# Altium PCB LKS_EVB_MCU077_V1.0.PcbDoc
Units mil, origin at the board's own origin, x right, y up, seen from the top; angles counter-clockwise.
Board outline 2625 x 1560 mil, 2 copper layers (Top Layer, Bottom Layer); 32 components, 57 nets, 146 pads, 20 vias.
Unrouted connection lines stored in the file: 4.
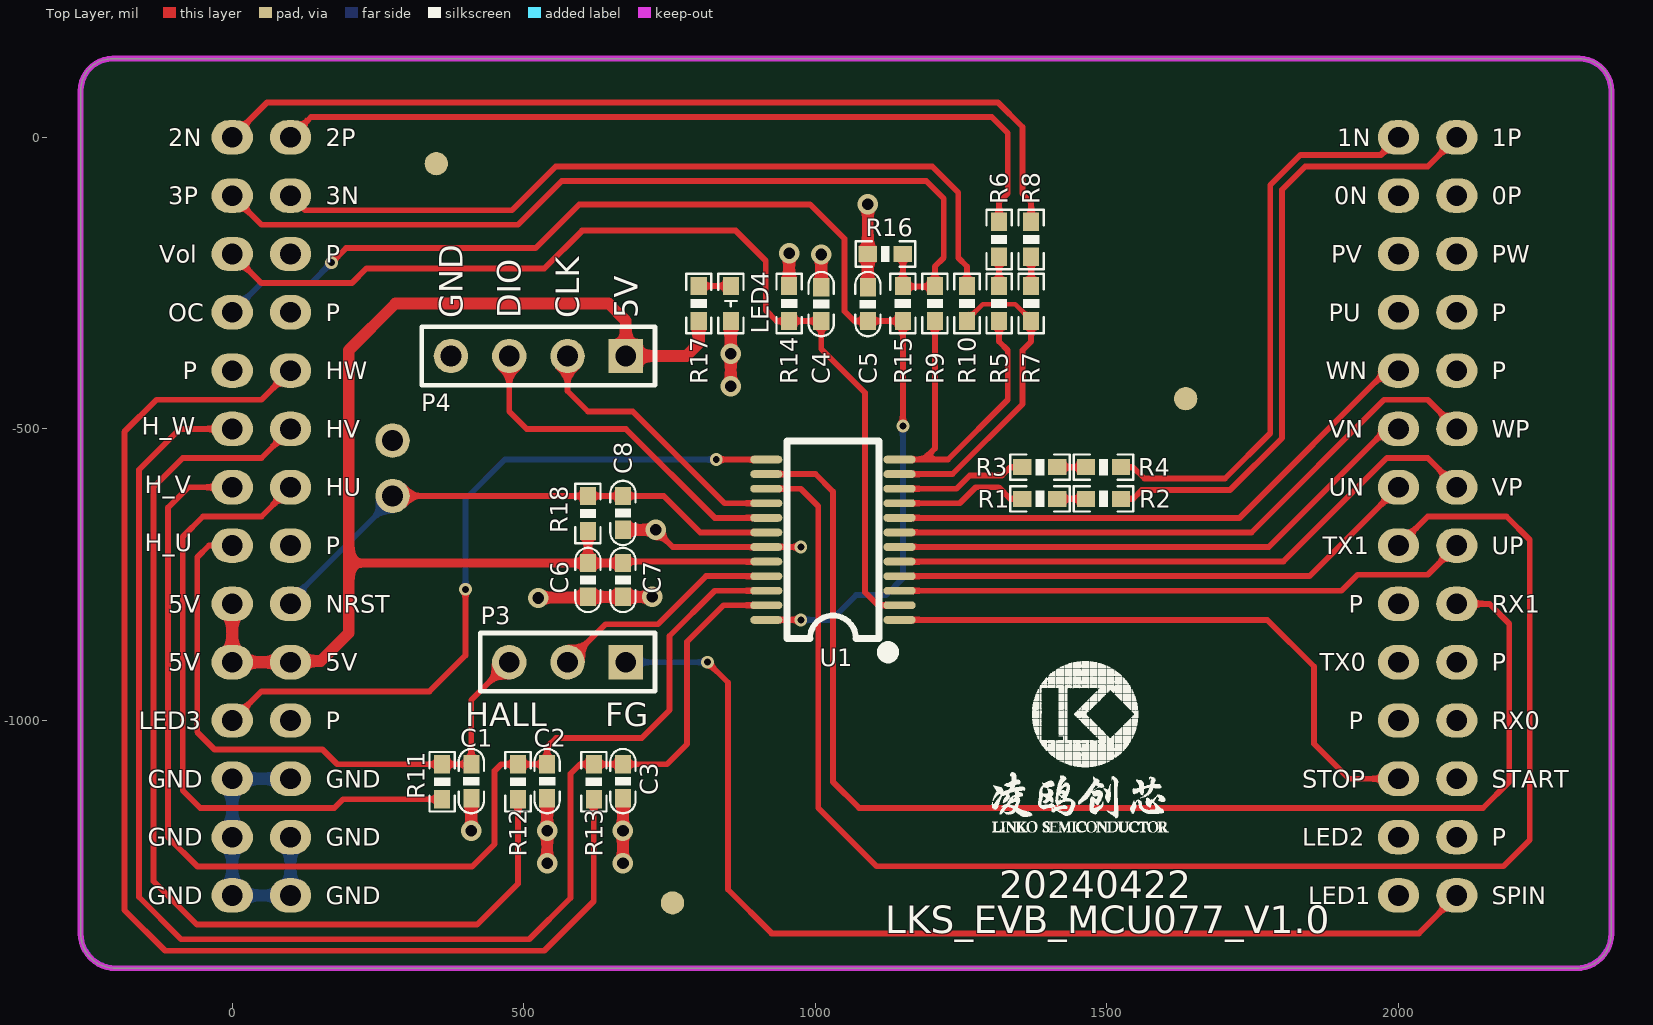
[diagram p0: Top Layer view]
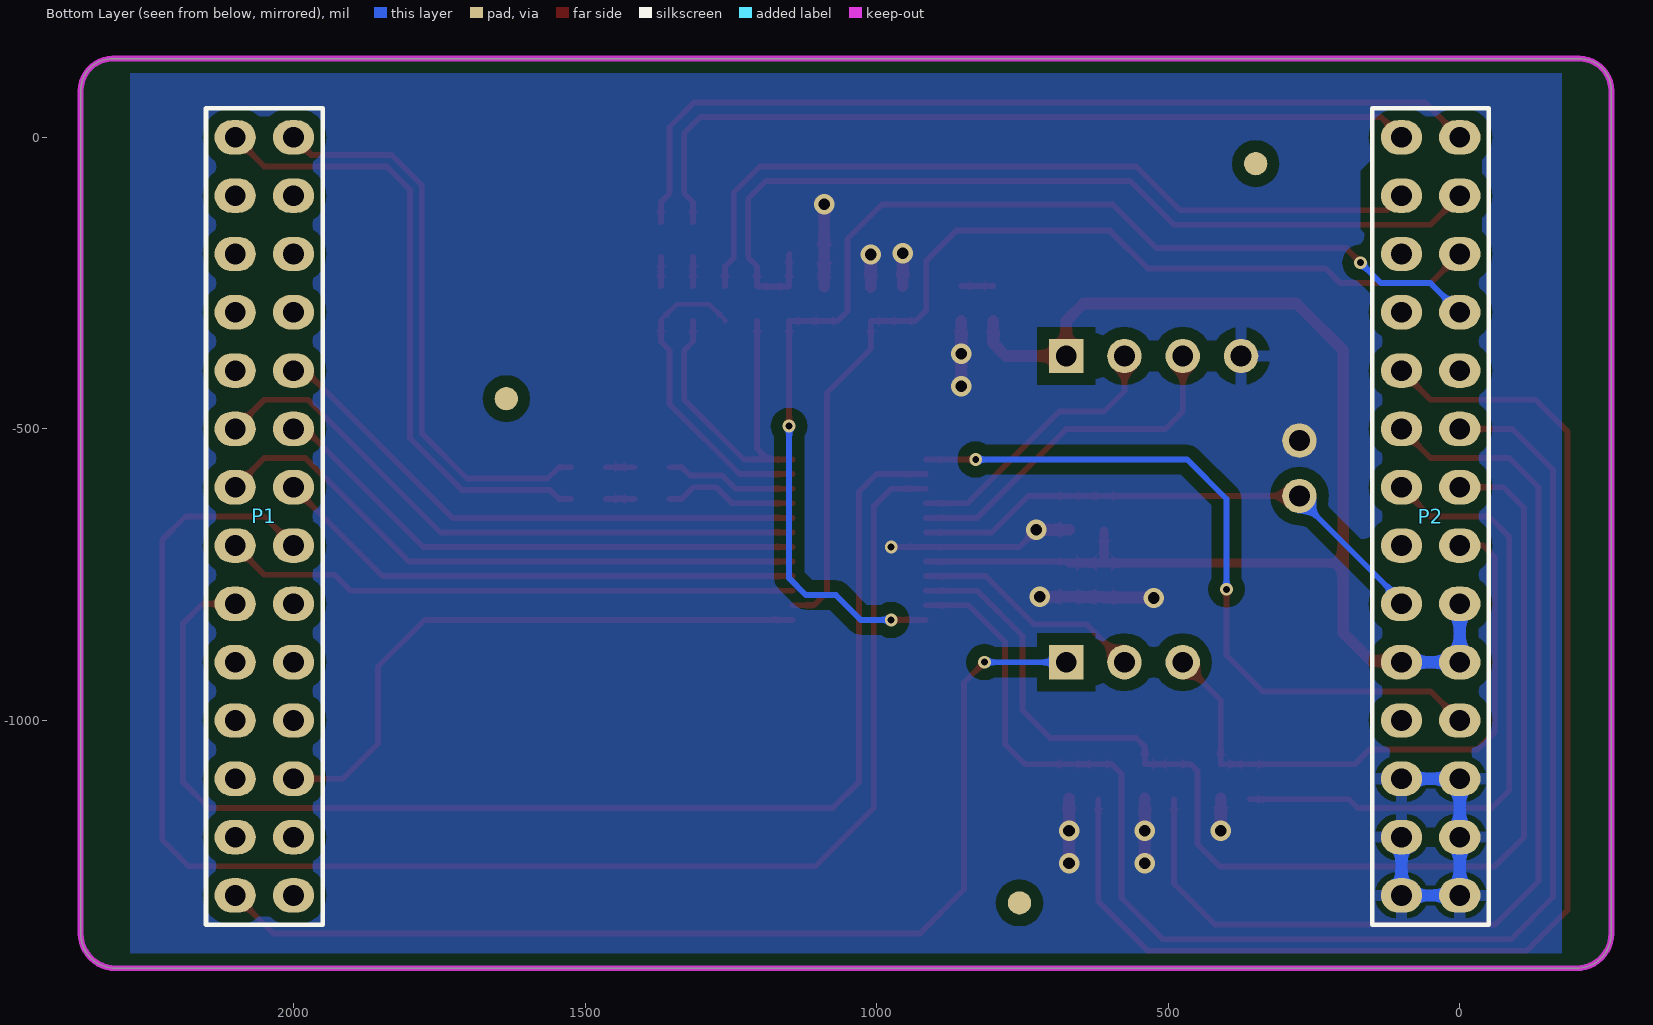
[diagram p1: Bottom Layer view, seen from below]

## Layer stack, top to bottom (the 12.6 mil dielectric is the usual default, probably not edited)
Top Solder: solder mask 0.4, Solder Resist, Dk 3.5
Top Layer: signal copper 1.4
Dielectric1: dielectric 12.6, FR-4, Dk 4.8
Bottom Layer: signal copper 1.4
Bottom Solder: solder mask 0.4, Solder Resist, Dk 3.5

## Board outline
-260,-1365 -260,80 cw(c-205,80) -205,135 2310,135 cw(c2310,80) 2365,80 2365,-1365 cw(c2305,-1365) 2305,-1425 -200,-1425 cw(c-200,-1365)

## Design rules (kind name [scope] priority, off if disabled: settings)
Clearance Clearance_2 [InPolygon] p1: gap=20 ignorepadtopadclearanceinfootprint=FALSE except(0: Arc-Hole Track-Hole SMDPad-Hole THPad-Hole Via-Hole Fill-Hole Poly-Hole Region-Hole Text-Hole)
Clearance Clearance_1 [All] p2: gap=7.87 ignorepadtopadclearanceinfootprint=FALSE except(0: Arc-Hole Track-Hole SMDPad-Hole THPad-Hole Via-Hole Fill-Hole Poly-Hole Region-Hole Text-Hole)
ComponentClearance [All] p1: gap=0 collisioncheckmode=3 verticalgap=0 showdistances=FALSE
FabricationTestpoint [(IsPad And (OnTopLayer Or OnBottomLayer))] p1: side=3 testpointundercomponent=TRUE minsize=40 maxsize=100 preferedsize=60 minholesize=0 maxholesize=40 preferedholesize=32 testpointgrid=1 allowsidetop=TRUE allowsidebottom=TRUE usegrid=TRUE gridtolerance=0.01
PolygonConnect PolygonConnect_2 [All vs HasFootprint('HDR 1X4')] p1: connectstyle=Relief reliefconductorwidth=20 reliefentries=4 polygonreliefangle="90 Angle" airgapwidth=20
PolygonConnect PolygonConnect_1 [HasFootprint('HDR 2X14 底层') vs InNet('GND')] p2: connectstyle=Relief reliefconductorwidth=20 reliefentries=4 polygonreliefangle="90 Angle" airgapwidth=10
PolygonConnect [All] p3: connectstyle=Direct reliefconductorwidth=10 reliefentries=4 polygonreliefangle="90 Angle" airgapwidth=10
RoutingVias [All] p1: holewidth=28 width=50 viastyle="Through Hole" minholewidth=28 minwidth=50 maxholewidth=28 maxwidth=50
SilkToSolderMaskClearance SilkscreenOverComponentPads [IsPad] p1: minsilkscreentomaskgap=10 clearancetoexposedcopper=TRUE
SolderMaskExpansion [All] p1: expansion=4 istentingtop=FALSE
Width [All] p1: maxlimit=100 minlimit=1 preferedwidth=10
27 further rules are at their usual default settings.

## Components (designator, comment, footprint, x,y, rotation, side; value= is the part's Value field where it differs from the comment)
C1 "10nF/16V" 0603C 410,-1104 r270 top
C2 "10nF/16V" 0603C 540,-1104 r270 top
C3 "10nF/16V" 0603C 670,-1104 r270 top
C4 "100nF/50V" 0603C 1010,-285.94 r270 top
C5 "1nF/50V" 0603C 1090,-285.94 r270 top
C6 "10uF/10V" 0603C 610,-759.05 r90 top
C7 "100nF/50V" 0603C 670,-759.05 r90 top
C8 "100nF/50V" 0603C 670,-644 r270 top
LED4 "LED" "LED 0603R" 855,-285 r270 top
P1 "Header 14X2A" "HDR 2X14 底层" 2000,0 r180 bottom locked
P2 "Header 14X2A" "HDR 2X14 底层" 0,0 r180 bottom locked
P3 "Header 3" "HDR 1X3" 675,-900 r180 top
P4 "Header 4" "HDR 1X4" 675,-375 r180 top locked
R1 "20K1%" 0603R 1385,-620 r180 top value=K
R2 "20K1%" 0603R 1494.06,-620 r180 top value=K
R3 "20K1%" 0603R 1385,-565.6 r180 top value=K
R4 "20K1%" 0603R 1494.06,-565.6 r180 top value=K
R5 "20K1%" 0603R 1315,-285 r270 top value=K
R6 "20K1%" 0603R 1315,-175 r270 top value=K
R7 "20K1%" 0603R 1370,-285 r270 top value=K
R8 "20K1%" 0603R 1370,-175 r270 top value=K
R9 "1K1%" 0603R 1205,-285 r270 top value=K
R10 "1K1%" 0603R 1260,-285 r270 top value=K
R11 "2K" 0603R 360,-1105 r90 top value=K
R12 "2K" 0603R 490,-1105 r90 top value=K
R13 "2K" 0603R 620,-1105 r90 top value=K
R14 "1K1%" 0603R 955,-285 r270 top value=K
R15 "1K1%" 0603R 1150,-285 r90 top value=K
R16 "10R" 0603R 1120,-200 r180 top value=K
R17 "330R" 0603R 800,-285 r90 top value=330
R18 "20K" 0603R 610,-645 r270 top value=K
U1 "LKS32MC077MBS8" SSOP24 1030,-690 r180 top

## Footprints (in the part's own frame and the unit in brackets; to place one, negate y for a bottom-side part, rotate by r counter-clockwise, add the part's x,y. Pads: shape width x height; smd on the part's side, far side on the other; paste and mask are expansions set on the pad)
0603C [mm] "电容"
  rect 0.8x0.7 smd: 1(-0.737,0) 2(0.738,0)
  silkscreen extent -1.4,-0.55 1.4,0.55, body extent -0.8,-0.41 0.8,0.41, height 0.81
0603R [mm] "电阻"
  rect 0.8x0.7 smd: 1(-0.762,0) 2(0.762,0)
  silkscreen extent -1.3,-0.55 1.3,0.55, body extent -0.8,-0.4 0.8,0.4, height 0.45
"HDR 1X3" [mm] "单排针 2.54mm"
  rect 1.5x1.5 hole 0.9: 1(0,0)
  round 1.5 hole 0.9: 2(2.54,0) 3(5.08,0)
  silkscreen extent -1.27,-1.27 6.35,1.27, body extent -1.27,-1.27 6.35,1.27, height 8.5
"HDR 1X4" [mm] "单排针 2.54mm"
  rect 1.5x1.5 hole 0.9: 1(0,0)
  round 1.5 hole 0.9: 2(2.54,0) 3(5.08,0) 4(7.62,0)
  silkscreen extent -1.27,-1.27 8.89,1.27, body extent -1.27,-1.27 8.89,1.27, height 8.5
"HDR 2X14 底层" [mm] "双排针 2.54mm 底层"
  oval 1.8x1.5 hole 0.9: 1(0,0) 2(0,-2.54) 3(0,-5.08) 4(0,-7.62) 5(0,-10.16) 6(0,-12.7) 7(0,-15.24) 8(0,-17.78) 9(0,-20.32) 10(0,-22.86) 11(0,-25.4) 12(0,-27.94) 13(0,-30.48) 14(0,-33.02) 15(-2.54,0) 16(-2.54,-2.54) 17(-2.54,-5.08) 18(-2.54,-7.62) 19(-2.54,-10.16) 20(-2.54,-12.7) 21(-2.54,-15.24) 22(-2.54,-17.78) 23(-2.54,-20.32) 24(-2.54,-22.86) 25(-2.54,-25.4) 26(-2.54,-27.94) 27(-2.54,-30.48) 28(-2.54,-33.02)
  silkscreen extent -3.81,-34.29 1.27,1.27, body extent -3.81,-34.29 1.27,1.27, height 8.5
"LED 0603R" [mm] "LED"
  rect 0.8x0.7 smd: 1(-0.762,0) 2(0.762,0)
  silkscreen extent -1.3,-0.55 1.3,0.55, body extent -0.8,-0.4 0.8,0.4, height 0.47
SSOP24 [mm] "e=0.635mm"
  oval 1.4x0.34 smd: 1(-2.9,3.492) 2(-2.9,2.857) 3(-2.9,2.222) 4(-2.9,1.587) 5(-2.9,0.952) 6(-2.9,0.317) 7(-2.9,-0.318) 8(-2.9,-0.953) 9(-2.9,-1.588) 10(-2.9,-2.223) 11(-2.9,-2.858) 12(-2.9,-3.492) 13(2.9,-3.492) 14(2.9,-2.857) 15(2.9,-2.222) 16(2.9,-1.587) 17(2.9,-0.952) 18(2.9,-0.317) 19(2.9,0.318) 20(2.9,0.953) 21(2.9,1.588) 22(2.9,2.223) 23(2.9,2.858) 24(2.9,3.492)
  silkscreen extent -2.5,-4.3 2,5, body extent -3.22,-3.84 3.19,3.96, height 1.03

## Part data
C1 C2 C3: library part CAP, "Capacitor"
C4 C5 C6 C7 C8: library part C, "Capacitor"
LED4: "LED_Light"
P1 P2: "Header, 14-Pin, Dual row"
P3: "Header, 3-Pin"
P4: "Header, 4-Pin"
R1 R2 R3 R4 R5 R6 R7 R8 R9 R10 R11 R12 R13 R14 R15 R16 R17 R18: library part Res, "Resistor"
U1: "芯片"

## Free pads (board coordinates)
  round 59 hole 36: 0(275,-520.01) 1(275,-615)
  round 40 all layers, no hole: 2(1635,-448.14) 3(755,-1312.82) 4(350,-45)

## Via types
v1: diameter 35, hole 20, Top Layer to Bottom Layer, 13 vias
v2: diameter 22, hole 12, Top Layer to Bottom Layer, 7 vias

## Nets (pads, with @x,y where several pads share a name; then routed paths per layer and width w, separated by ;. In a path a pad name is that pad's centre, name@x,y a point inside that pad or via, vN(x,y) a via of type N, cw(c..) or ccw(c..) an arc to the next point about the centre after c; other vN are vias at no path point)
+5V: C6.2 C7.2 P2.9 P2.10 P2.24 P4.1 R17.1 R18.2 U1.20 | length 2530.6
  Top Layer w10: C7.2 672.5,-727.5 U1.20
  Top Layer w15: 200,-730 C6.2 ; R18.2 C6.2 ; C7.2 C6.2
  Top Layer w20: P2.9 P2.10 P2.24 102.03,-897.97 152.03,-897.97 200,-850 200,-730 200,-365 280,-285 645.31,-285 675,-314.68 P4.1 778.35,-375 800,-353.35 R17.1
  Bottom Layer w20: P2.9 P2.10 P2.24
GND: C1.2 C2.2 C3.2 C4.1 C5.1 C6.1 C7.1 C8.2 LED4.2 P2.12 P2.13 P2.14 P2.16 P2.26 P2.27 P2.28 P4.4 pad.0 R10.1 R14.1 R16.2 U1.19 | length 3029.4
  Top Layer w10: P2.16 125,-125 479.64,-125 554.64,-50 1200.36,-50 1245,-94.64 1245,-206.5 1260,-221.5 R10.1 ; v1(726,-673.05) 755.45,-702.5 U1.19 v2(975,-702.5)
  Top Layer w20: v1(410,-1189.06) C1.2 ; v1(525,-790) 525.97,-789.03 609.03,-789.03 C6.1 C7.1 v1(720,-788.05) ; v1(540,-1245.06) v1(540,-1189.06) C2.2 ; v1(670,-1245.06) v1(670,-1189.06) C3.2 ; C8.2 v1(726,-673.05) ; v1(855,-427) v1(855,-371) LED4.2 ; R14.1 v1(955,-199) ; C4.1 v1(1010,-200.94) ; C5.1@1090,-255.94 v1(1090,-115)
  Bottom Layer w20: P2.27 P2.28 P2.14 P2.13 P2.12 P2.26
HALL_U: C1.1 P2.8 P3.3 R11.2 | length 1063
  Top Layer w10: P2.8 -40,-700 -60,-720 -60,-1020 -30,-1050 155,-1050 180,-1075 R11.2 C1.1 410,-965 P3.3
HALL_V: C2.1 P2.7 R12.2 U1.22 | length 2097.8
  Top Layer w10: P2.7 -75,-600 -110,-635 -110,-1200 -59.36,-1250.64 411.01,-1250.64 450,-1211.65 450,-1086.28 461.28,-1075 R12.2 C2.1 540,-1045 555,-1030 702.22,-1030 750,-982.22 750,-855 827.5,-777.5 U1.22
HALL_W: C3.1 P2.6 R13.2 U1.23 | length 2492.3
  Top Layer w10: P2.6 -90,-500 -160,-570 -160,-1302.87 -87.87,-1375 509.25,-1375 580,-1304.25 580,-1091.28 596.28,-1075 R13.2 C3.1 745.54,-1075 780,-1040.54 780,-865 842.5,-802.5 U1.23
HU: P2.21 R11.1 | length 1118.8
  Top Layer w10: P2.21 50,-650 -50,-650 -85,-685 -85,-1120 -55,-1150 175,-1150 190,-1135 R11.1
HV: P2.20 R12.1 | length 1781.9
  Top Layer w10: P2.20 50,-550 -85,-550 -135,-600 -135,-1275.64 -60.64,-1350 420,-1350 490,-1280 R12.1
HW: P2.19 R13.1 | length 2192.7
  Top Layer w10: P2.19 50,-450 -130,-450 -185,-505 -185,-1325 -115,-1395 535,-1395 620,-1310 R13.1
LED1: P1.14
LED2: P1.13
LED3: P2.11 U1.13 | length 1258.4
  Top Layer w10: P2.11 50,-950 338.35,-950 400,-888.35 v2(400,-775) ; v2(830,-552.5) U1.13
  Bottom Layer w10: v2(400,-775) 400,-620 467.5,-552.5 v2(830,-552.5)
NetLED4_1: LED4.1 R17.2 | length 55
  Top Layer w10: R17.2 LED4.1
NetP3_2: P3.2 U1.21 | length 401.9
  Top Layer w10: P3.2 640,-835 730,-835 812.5,-752.5 U1.21
NetR1_1: R1.1 R2.2 | length 49.1
  Top Layer w10: R1.1 R2.2
NetR3_1: R3.1 R4.2 | length 49.1
  Top Layer w10: R3.1 R4.2
NetR5_1: R5.1 R6.2 | length 50
  Top Layer w10: R5.1 R6.2
NetR7_1: R7.1 R8.2 | length 50
  Top Layer w10: R7.1 R8.2
NRST: C8.1 P2.23 pad.1 R18.1 U1.18 | length 924.2
  Top Layer w10: pad.1 R18.1 C8.1 740,-615 802.5,-677.5 U1.18
  Bottom Layer w10: P2.23 100,-795 275,-620 pad.1
OC: C5.2 P2.4 R15.1 U1.24 | length 2087
  Top Layer w10: v2(170,-215) 195,-190 520,-190 595,-115 991.01,-115 1050,-173.99 1050,-298.15 1066.85,-315 C5.2 R15.1 v2(1150,-495) ; U1.24 v2(975,-827.5)
  Bottom Layer w10: P2.4 50,-250 135,-250 v2(170,-215) ; v2(975,-827.5) 1027.13,-827.5 1069.63,-785 1120.93,-785 1150,-755.93 v2(1150,-495)
OPA2_IN: R3.2 U1.10 | length 226.1
  Top Layer w10: U1.10 1242.07,-602.5 1264.57,-580 1319.85,-580 1334.25,-565.6 R3.2
OPA2_IP: R1.2 U1.9 | length 230.5
  Top Layer w10: U1.9 1247.5,-627.5 1275,-600 1314.25,-600 1334.25,-620 R1.2
OPA3_IN: R7.2 R10.2 U1.11 | length 545.6
  Top Layer w8: R10.2 1260,-313.03 1287.09,-285.94 1342.91,-285.94 1370,-313.03 R7.2
  Top Layer w10: U1.11 1235,-577.5 1355,-457.5 1355,-365 1370,-350 R7.2
OPA3_IP: R5.2 R9.2 U1.12 | length 614.9
  Top Layer w10: U1.12 1185.84,-552.5 ; R9.2 1205,-533.34 1185.84,-552.5 ; R5.2 1315,-350 1330,-365 1330,-450 1227.5,-552.5 1185.84,-552.5
P0.0: P2.22
P0.4: P1.27
P0.14: P1.11
P1.3: P1.24
P1.10: P1.19
P1.11: P1.18
P2.1: P2.18
P2.2: P2.5
P2.7: P1.9
P2.10: P2.17
P3.2: P2.25
PGND: P1.1 P1.2 P2.1 P2.2 R4.1 R8.1 R9.1 R15.2 R16.1 | length 4094.2
  Top Layer w10: P2.2 50,-150 490,-150 565,-75 1190,-75 1220,-105 1220,-206.26 1205,-221.26 R9.1 1204.06,-255.94 1150,-255.94 1150,-200.94 R16.1@1149.06,-200 ; P2.1 60,60 1312.86,60 1355,17.86 1355,-96.5 1370,-111.5 R8.1 ; R4.1 1544.8,-565.6 1564.21,-585 1702.5,-585 1780,-507.5 1780,-81.72 1831.72,-30 1970,-30 P1.1
PU: P1.4
PV: P1.3
PW: P1.17
RXD0: P1.25
RXD1: P1.23 U1.14 | length 2196.4
  Top Layer w10: U1.14 1000,-577.5 1030,-607.5 1030,-1105 1075,-1150 2145,-1150 2190,-1105 2190,-834.14 2155.86,-800 P1.23
SPIN: P1.28 P3.1 | length 1852.5
  Top Layer w10: v2(815,-900) 850,-935 850,-1290 925,-1365 2035,-1365 P1.28
  Bottom Layer w10: P3.1 v2(815,-900)
START1: P1.26
STOP1: P1.12 U1.1 | length 1046.3
  Top Layer w10: U1.1 1775,-827.5 1855,-907.5 1855,-1040 1915,-1100 P1.12
SWCLK: P4.2 U1.16 | length 480.6
  Top Layer w10: P4.2 575,-435 610,-470 686.74,-470 844.24,-627.5 U1.16
SWDIO: P4.3 U1.17 | length 611.4
  Top Layer w10: P4.3 475,-470 505,-500 675,-500 827.5,-652.5 U1.17
TXD0: P1.10
TXD1: P1.8 U1.15 | length 2676.4
  Top Layer w10: U1.15 975,-602.5 1005,-632.5 1005,-1150 1105,-1250 2180,-1250 2225,-1205 2225,-690 2185,-650 2050,-650 P1.8
UN: P1.7 U1.4 | length 919
  Top Layer w10: U1.4 1847.5,-752.5 P1.7
UP: P1.22 U1.3 | length 987.9
  Top Layer w10: U1.3 1902.18,-777.5 1929.68,-750 2050,-750 P1.22
UP-: P2.15 R6.1 | length 1414.6
  Top Layer w10: P2.15 135,35 1302.5,35 1330,7.5 1330,-96.26 1315,-111.26 R6.1
VN: P1.6 U1.6 | length 939.7
  Top Layer w10: U1.6 1777.5,-702.5 1980,-500 P1.6
VOL_ADC: C4.2 P2.3 R14.2 U1.2 | length 1746.6
  Top Layer w10: P2.3 50,-250 205,-250 230,-225 535,-225 600,-160 863.43,-160 915,-211.57 915,-296.65 933.35,-315 R14.2 C4.2 1010,-363.05 1085,-438.05 1085,-780 1107.5,-802.5 U1.2
VP: P1.21 U1.5 | length 1050.1
  Top Layer w10: U1.5 1802.5,-727.5 1980,-550 2050,-550 P1.21
VP-: P1.15 R2.1 | length 1082.2
  Top Layer w10: R2.1 1544.8,-620 1559.8,-605 1710.78,-605 1800,-515.78 1800,-90 1840,-50 2050,-50 P1.15
WN: P1.5 U1.8 | length 960.4
  Top Layer w10: U1.8 1727.5,-652.5 1980,-400 P1.5
WP: P1.20 U1.7 | length 1070.8
  Top Layer w10: U1.7 1747.78,-677.5 1975.28,-450 2050,-450 P1.20
WP-: P1.16

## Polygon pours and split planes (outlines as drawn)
GND on Bottom Layer "Bottom Layer-No Net 1" (solid, remove dead copper, pour order 12): -175,135 -175,-1425 2280,-1425 2280,135

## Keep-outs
Keep-Out Layer:
  the board outline again, w10

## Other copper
Bottom Layer:
  pour cut-out: -37.49,-37.49 150,-37.49 170,-57.49 170,-157.49 154.98,-172.51 -37.49,-172.51

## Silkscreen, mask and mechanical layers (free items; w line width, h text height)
Top Overlay:
  drawing of 144 lines, arcs and shapes, not listed
  text "2N" at -110,-15 h30
  text "2P" at 160,-15 h30
  text "1N" at 1895,-15 h30
  text "1P" at 2160,-15 h30
  text "3P" at -110,-115 h30
  text "3N" at 160,-115 h30
  text "0N" at 1890,-115 h30
  text "0P" at 2160,-115 h30
  text "Vol" at -125,-215 h30
  text "P" at 160,-215 h30
  text "PV" at 1885,-215 h30
  text "PW" at 2160,-215 h30
  text "GND" at 395,-310 h40 r90
  text "DIO" at 495,-310 h40 r90
  text "CLK" at 595,-310 h40 r90
  text "5V" at 695,-310 h40 r90
  text "OC" at -110,-315 h30
  text "P" at 160,-315 h30
  text "PU" at 1880,-315 h30
  text "P" at 2160,-315 h30
  text "P" at -85,-415 h30
  text "HW" at 160,-415 h30
  text "WN" at 1875,-415 h30
  text "P" at 2160,-415 h30
  text "H_W" at -155,-510 h30
  text "HV" at 160,-515 h30
  text "VN" at 1880,-515 h30
  text "WP" at 2160,-515 h30
  text "H_V" at -150,-610 h30
  text "HU" at 160,-615 h30
  text "UN" at 1880,-615 h30
  text "VP" at 2160,-615 h30
  text "H_U" at -150,-710 h30
  text "P" at 160,-715 h30
  text "TX1" at 1870,-715 h30
  text "UP" at 2160,-715 h30
  text "5V" at -110,-815 h30
  text "NRST" at 160,-815 h30
  text "P" at 1915,-815 h30
  text "RX1" at 2160,-815 h30
  text "5V" at -110,-915 h30
  text "5V" at 160,-915 h30
  text "TX0" at 1865,-915 h30
  text "P" at 2160,-915 h30
  text "HALL" at 400,-1010 h40
  text "FG" at 640,-1010 h40
  text "LED3" at -160,-1015 h30
  text "P" at 160,-1015 h30
  text "P" at 1915,-1015 h30
  text "RX0" at 2160,-1015 h30
  text "GND" at -145,-1115 h30
  text "GND" at 160,-1115 h30
  text "STOP" at 1835,-1115 h30
  text "START" at 2160,-1115 h30
  text "GND" at -145,-1215 h30
  text "GND" at 160,-1215 h30
  text "LED2" at 1835,-1215 h30
  text "P" at 2160,-1215 h30
  text "GND" at -145,-1315 h30
  text "GND" at 160,-1315 h30
  text "LED1" at 1845,-1315 h30
  text "SPIN" at 2160,-1315 h30
  text "20240422" at 1315,-1320 h80
  text "LKS_EVB_MCU077_V1.0" at 1120,-1380 h80
Top Solder:
  circle w78: c1635,-448.14 r17
  circle w78: c755,-1312.82 r17
  circle w78: c350,-45 r17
